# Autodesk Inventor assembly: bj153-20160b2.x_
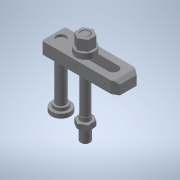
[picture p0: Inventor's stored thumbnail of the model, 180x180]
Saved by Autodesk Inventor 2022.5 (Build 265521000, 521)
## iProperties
Part Number: bj153-20160b2.x_
Material: 一般
Document SubType Name: Assembly
Designer: ImaoCorp
Sending System: SOLIDWORKS 2017-2017317
MC: AMD64
MC_MODEL: Intel64 Family 6 Model 60 Stepping 3, GenuineIntel
OS: Windows_NT
FRU: Parasolid Version 29.0, build 201,  4-17-2017
FORMAT: text
GUISE: transmit
KEY: bj153-20160b2
FILE: bj153-20160b2.x_t
DATE: Fri Mar 15 10:22:30 2019
Author: ImaoCorp
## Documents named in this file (6)
- X:\14_SW2022-Inv2022\00_全2023-1023新製品(TCC)まで\b\bj153-20160b2\BJ153-20160B2.iam
- X:\14_SW2022-Inv2022\00_全2023-1023新製品(TCC)まで\b\bj153-20160b2\bj153-20160b2_01.ipt
- X:\14_SW2022-Inv2022\00_全2023-1023新製品(TCC)まで\b\bj153-20160b2\bj153-20160b2_02.ipt
- X:\14_SW2022-Inv2022\00_全2023-1023新製品(TCC)まで\b\bj153-20160b2\bj153-20160b2_03.ipt
- X:\14_SW2022-Inv2022\00_全2023-1023新製品(TCC)まで\b\bj153-20160b2\bj153-20160b2_04.ipt
- X:\14_SW2022-Inv2022\00_全2023-1023新製品(TCC)まで\b\bj153-20160b2\bj153-20160b2_05.ipt
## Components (5 placed, 5 different names)
1. bj153-20160b2_01
2. bj153-20160b2_02
3. bj153-20160b2_03
4. bj153-20160b2_04
5. bj153-20160b2_05
